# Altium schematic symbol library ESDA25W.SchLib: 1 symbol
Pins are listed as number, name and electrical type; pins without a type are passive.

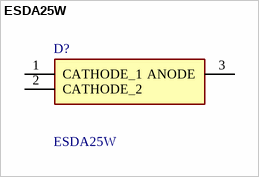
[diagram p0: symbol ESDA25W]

## ESDA25W
designator D?
STMicroelectronics ESDA25W Dual Uni-Directional TVS Diode Array, 400W peak, 3-Pin SOT-323; Geometry.Height: 1.1mm
footprint SOT65P210X110-3N
pins: 1 CATHODE_1, 2 CATHODE_2, 3 ANODE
